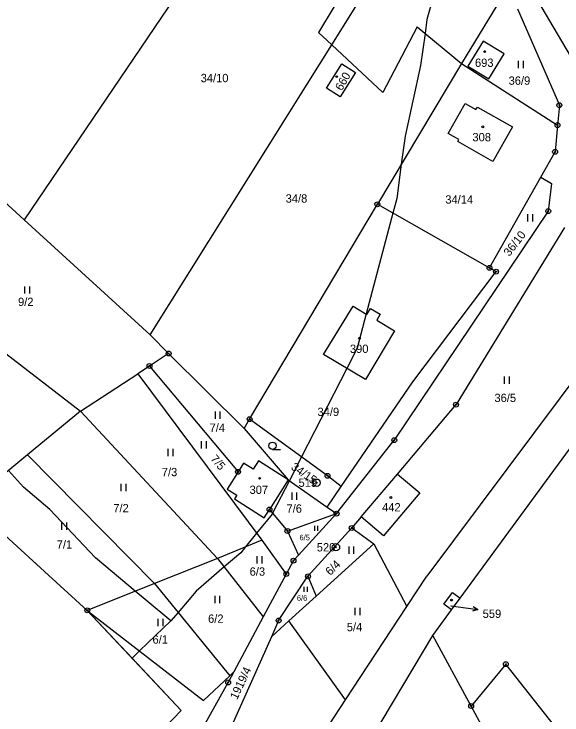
# Model space of a CAD drawing. Extents: x -445050 to -440454, y -1134563 to -1129741.
# Drawn here: x -442906.4 to -442794.3, y -1131013.5 to -1130870 of the extents above; entities that cross this region are included whole.
import ezdxf

# ---------------------------------------------------------------- set-up
doc = ezdxf.new("R2010")
doc.units = 0
for name, color, linetype in [('Vrstva 1', 7, 'Continuous'), ('Vrstva 13', 7, 'Continuous'), ('Vrstva 16', 7, 'Continuous'), ('Vrstva 17', 7, 'Continuous'), ('Vrstva 18', 7, 'Continuous'), ('Vrstva 19', 7, 'Continuous'), ('Vrstva 24', 7, 'Continuous'), ('Vrstva 25', 7, 'Continuous'), ('Vrstva 3', 7, 'Continuous'), ('Vrstva 37', 7, 'Continuous'), ('Vrstva 52', 7, 'Continuous')]:
    doc.layers.add(name, color=color, linetype=linetype)

msp = doc.modelspace()

# ---------------------------------------------------------------- linework, layer by layer
at = {"layer": 'Vrstva 1'}
for p, q in [((-442861.86, -1130849.44), (-442904.31, -1130912.16)), ((-442810.44, -1130875.57), (-442813.56, -1130880.71)), ((-442806.16, -1130878.16), (-442810.44, -1130875.57)), ((-442809.29, -1130883.3), (-442806.16, -1130878.16)), ((-442813.56, -1130880.71), (-442809.29, -1130883.3))]:
    msp.add_line(p, q, dxfattribs=at)
for points in [[(-442841.41, -1130876.33), (-442815.8, -1130835.42)], [(-442828.1, -1130847.15), (-442844.09, -1130873.84)], [(-442804.94, -1130863.83), (-442814.89, -1130880.18)], [(-442800.19, -1130865.72), (-442789.28, -1130884.24)], [(-442803.42, -1130868.95), (-442794.84, -1130888.7)], [(-442823.94, -1130872.69), (-442830.94, -1130886.07)], [(-442823.94, -1130872.69), (-442814.89, -1130880.18)], [(-442841.41, -1130876.33), (-442844.09, -1130873.84)], [(-442846.45, -1130884.39), (-442841.41, -1130876.33)], [(-442830.94, -1130886.07), (-442841.41, -1130876.33)], [(-442842.49, -1130885.21), (-442839.35, -1130880.2)], [(-442839.35, -1130880.2), (-442836.53, -1130881.97)], [(-442814.89, -1130880.18), (-442832.06, -1130908.96)], [(-442814.89, -1130880.18), (-442795.21, -1130892.76)], [(-442836.53, -1130881.97), (-442839.67, -1130886.99)], [(-442878.56, -1130935.7), (-442846.45, -1130884.39)], [(-442839.67, -1130886.99), (-442842.49, -1130885.21)], [(-442817.57, -1130894.46), (-442814.08, -1130888.34)], [(-442814.08, -1130888.34), (-442811.9, -1130889.58)], [(-442794.84, -1130888.7), (-442795.21, -1130892.76)], [(-442811.9, -1130889.58), (-442811.6, -1130889.06)], [(-442811.6, -1130889.06), (-442804.43, -1130893.14)], [(-442804.43, -1130893.14), (-442808.46, -1130900.22)], [(-442795.21, -1130892.76), (-442795.71, -1130898.24)], [(-442815.38, -1130895.71), (-442817.57, -1130894.46)], [(-442815.63, -1130896.14), (-442815.38, -1130895.71)], [(-442808.46, -1130900.22), (-442815.63, -1130896.14)], [(-442798.63, -1130903.39), (-442795.71, -1130898.24)], [(-442809.14, -1130921.97), (-442798.63, -1130903.39)], [(-442798.63, -1130903.39), (-442796.47, -1130904.73)], [(-442910.91, -1130906.11), (-442904.31, -1130912.16)], [(-442796.47, -1130904.73), (-442797.11, -1130910.38)], [(-442858.2, -1130952.92), (-442832.06, -1130908.96)], [(-442832.06, -1130908.96), (-442809.14, -1130921.97)], [(-442797.11, -1130910.38), (-442828.61, -1130957.23)], [(-442904.31, -1130912.16), (-442878.56, -1130935.7)], [(-442793.77, -1130913.74), (-442815.97, -1130949.95)], [(-442772.87, -1130919.37), (-442821.98, -1130985.08)], [(-442929.68, -1130922.83), (-442892.79, -1130951.31)], [(-442824.84, -1130945.29), (-442807.79, -1130922.74)], [(-442809.14, -1130921.97), (-442807.79, -1130922.74)], [(-442843.07, -1130939.7), (-442837, -1130929.82)], [(-442837, -1130929.82), (-442834.19, -1130931.5)], [(-442834.19, -1130931.5), (-442833.46, -1130930.29)], [(-442833.46, -1130930.29), (-442831.47, -1130931.47)], [(-442831.47, -1130931.47), (-442832.2, -1130932.69)], [(-442832.2, -1130932.69), (-442828.56, -1130934.85)], [(-442878.56, -1130935.7), (-442874.76, -1130939.49)], [(-442828.56, -1130934.85), (-442834.49, -1130944.81)], [(-442815.11, -1130989.54), (-442775.83, -1130936)], [(-442874.76, -1130939.49), (-442878.66, -1130942.05)], [(-442874.76, -1130939.49), (-442859.34, -1130954.86)], [(-442834.49, -1130944.81), (-442843.07, -1130939.7)], [(-442878.66, -1130942.05), (-442881.05, -1130943.62)], [(-442878.66, -1130942.05), (-442860.57, -1130963.71)], [(-442892.79, -1130951.31), (-442881.05, -1130943.62)], [(-442881.05, -1130943.62), (-442855.7, -1130977.68)], [(-442839.48, -1130966.72), (-442824.84, -1130945.29)], [(-442827.97, -1130964.15), (-442815.97, -1130949.95)], [(-442892.79, -1130951.31), (-442903.63, -1130960.22)], [(-442864.74, -1130981.44), (-442892.79, -1130951.31)], [(-442859.34, -1130954.86), (-442858.2, -1130952.92)], [(-442842.26, -1130964.51), (-442858.2, -1130952.92)], [(-442859.34, -1130954.86), (-442850.29, -1130965.33)], [(-442840.41, -1130972.26), (-442828.61, -1130957.23)], [(-442903.63, -1130960.22), (-442915.59, -1130970.05)], [(-442877.63, -1130986.57), (-442903.63, -1130960.22)], [(-442859.43, -1130961.91), (-442860.57, -1130963.71)], [(-442857.45, -1130963.17), (-442859.43, -1130961.91)], [(-442856.37, -1130961.48), (-442857.45, -1130963.17)], [(-442850.29, -1130965.33), (-442856.37, -1130961.48)], [(-442860.57, -1130963.71), (-442862.8, -1130967.23)], [(-442839.48, -1130966.72), (-442842.26, -1130964.51)], [(-442835.4, -1130972.93), (-442827.97, -1130964.15)], [(-442827.97, -1130964.15), (-442823.39, -1130968.02)], [(-442850.29, -1130965.33), (-442854.14, -1130971.41)], [(-442850.29, -1130965.33), (-442842.34, -1130970.91)], [(-442862.8, -1130967.23), (-442860.82, -1130968.49)], [(-442842.34, -1130970.91), (-442839.48, -1130966.72)], [(-442860.82, -1130968.49), (-442861.3, -1130969.25)], [(-442861.3, -1130969.25), (-442855.22, -1130973.1)], [(-442823.39, -1130968.02), (-442830.82, -1130976.8)], [(-442855.22, -1130973.1), (-442854.14, -1130971.41)], [(-442854.14, -1130971.41), (-442850.46, -1130975.82)], [(-442842.34, -1130970.91), (-442840.41, -1130972.26)], [(-442850.46, -1130975.82), (-442840.41, -1130972.26)], [(-442848.23, -1130980.78), (-442840.41, -1130972.26)], [(-442835.4, -1130972.93), (-442837.31, -1130975.19)], [(-442830.82, -1130976.8), (-442835.4, -1130972.93)], [(-442850.46, -1130975.82), (-442848.23, -1130980.78)], [(-442837.31, -1130975.19), (-442846.26, -1130985.08)], [(-442837.31, -1130975.19), (-442832.78, -1130978.42)], [(-442855.7, -1130977.68), (-442864.74, -1130981.44)], [(-442855.7, -1130977.68), (-442850.7, -1130984.61)], [(-442844.6, -1130989.14), (-442832.78, -1130978.42)], [(-442832.78, -1130978.42), (-442826.03, -1130991.26)], [(-442864.74, -1130981.44), (-442877.63, -1130986.57)], [(-442864.74, -1130981.44), (-442855.41, -1130993.4)], [(-442849.23, -1130981.87), (-442850.7, -1130984.61)], [(-442849.23, -1130981.87), (-442848.23, -1130980.78)], [(-442850.7, -1130984.61), (-442855.41, -1130993.4)], [(-442852.26, -1130994.12), (-442846.26, -1130985.08)], [(-442846.26, -1130985.08), (-442844.6, -1130989.14)], [(-442826.03, -1130991.26), (-442821.98, -1130985.08)], [(-442877.63, -1130986.57), (-442891.39, -1130992.04)], [(-442877.63, -1130986.57), (-442862.27, -1131005.42)], [(-442850.2, -1130994.22), (-442844.6, -1130989.14)], [(-442818.49, -1130990.78), (-442816.72, -1130988.36)], [(-442816.72, -1130988.36), (-442815.11, -1130989.54)], [(-442816.88, -1130991.96), (-442815.11, -1130989.54)], [(-442891.39, -1130992.04), (-442867.66, -1131010.46)], [(-442838.56, -1131010.38), (-442826.03, -1130991.26)], [(-442820.71, -1130997.18), (-442816.88, -1130991.96)], [(-442816.88, -1130991.96), (-442818.49, -1130990.78)], [(-442855.41, -1130993.4), (-442861.42, -1131004.62)], [(-442852.26, -1130994.12), (-442853.74, -1130997.43)], [(-442853.74, -1130997.43), (-442850.2, -1130994.22)], [(-442838.56, -1131010.38), (-442850.2, -1130994.22)], [(-442853.74, -1130997.43), (-442865.98, -1131024.86)], [(-442833.2, -1131018.12), (-442820.71, -1130997.18)], [(-442812.87, -1131011.62), (-442820.71, -1130997.18)], [(-442805.78, -1131003.06), (-442812.87, -1131011.62)], [(-442793.04, -1131019.25), (-442805.78, -1131003.06)], [(-442861.42, -1131004.62), (-442862.58, -1131006.79)], [(-442862.27, -1131005.42), (-442861.42, -1131004.62)], [(-442867.66, -1131010.46), (-442862.27, -1131005.42)], [(-442873.47, -1131026.38), (-442862.58, -1131006.79)], [(-442859, -1131041.59), (-442838.56, -1131010.38)], [(-442803.93, -1131028.07), (-442812.87, -1131011.62)]]:
    msp.add_lwpolyline(points, dxfattribs=at)
at = {"layer": 'Vrstva 13'}
for points in [[(-442899.33, -1130984.82), (-442915.59, -1130970.05)], [(-442895.35, -1130988.44), (-442899.33, -1130984.82)], [(-442891.39, -1130992.04), (-442895.35, -1130988.44)], [(-442891.39, -1130992.04), (-442872.21, -1131012.5)], [(-442872.21, -1131012.5), (-442878.7, -1131019.3)]]:
    msp.add_lwpolyline(points, dxfattribs=at)
at = {"layer": 'Vrstva 16'}
msp.add_line((-442814.5, -1130991.47), (-442811.53, -1130991.88), dxfattribs=at)
for points in [[(-442817.02, -1130991.12), (-442814.5, -1130991.47)], [(-442812.45, -1130991.25), (-442811.53, -1130991.88), (-442812.59, -1130992.24)]]:
    msp.add_lwpolyline(points, dxfattribs=at)
at = {"layer": 'Vrstva 24'}
for centre, radius in [((-442794.84, -1130888.7), 0.5), ((-442794.84, -1130888.7), 0.1), ((-442795.21, -1130892.76), 0.5), ((-442795.21, -1130892.76), 0.1), ((-442795.71, -1130898.24), 0.5), ((-442795.71, -1130898.24), 0.1), ((-442832.06, -1130908.96), 0.5), ((-442832.06, -1130908.96), 0.1), ((-442797.11, -1130910.38), 0.5), ((-442797.11, -1130910.38), 0.1), ((-442809.14, -1130921.97), 0.5), ((-442809.14, -1130921.97), 0.1), ((-442807.79, -1130922.74), 0.5), ((-442807.79, -1130922.74), 0.1), ((-442874.76, -1130939.49), 0.5), ((-442874.76, -1130939.49), 0.1), ((-442878.66, -1130942.05), 0.5), ((-442878.66, -1130942.05), 0.1), ((-442815.97, -1130949.95), 0.5), ((-442815.97, -1130949.95), 0.1), ((-442858.2, -1130952.92), 0.5), ((-442858.2, -1130952.92), 0.1), ((-442828.61, -1130957.23), 0.5), ((-442828.61, -1130957.23), 0.1), ((-442860.57, -1130963.71), 0.5), ((-442860.57, -1130963.71), 0.1), ((-442842.26, -1130964.51), 0.5), ((-442842.26, -1130964.51), 0.1), ((-442844.5, -1130965.92), 0.75), ((-442844.5, -1130965.92), 0.1), ((-442854.14, -1130971.41), 0.5), ((-442854.14, -1130971.41), 0.1), ((-442840.41, -1130972.26), 0.5), ((-442840.41, -1130972.26), 0.1), ((-442837.31, -1130975.19), 0.5), ((-442850.46, -1130975.82), 0.5), ((-442850.46, -1130975.82), 0.1), ((-442837.31, -1130975.19), 0.1), ((-442840.53, -1130979.14), 0.75), ((-442840.53, -1130979.14), 0.1), ((-442849.23, -1130981.87), 0.5), ((-442849.23, -1130981.87), 0.1), ((-442850.7, -1130984.61), 0.5), ((-442850.7, -1130984.61), 0.1), ((-442846.26, -1130985.08), 0.5), ((-442846.26, -1130985.08), 0.1), ((-442891.39, -1130992.04), 0.5), ((-442891.39, -1130992.04), 0.1), ((-442852.26, -1130994.12), 0.5), ((-442852.26, -1130994.12), 0.1), ((-442805.78, -1131003.06), 0.5), ((-442805.78, -1131003.06), 0.1), ((-442862.58, -1131006.79), 0.5), ((-442862.58, -1131006.79), 0.1), ((-442812.87, -1131011.62), 0.5), ((-442812.87, -1131011.62), 0.1)]:
    msp.add_circle(centre, radius, dxfattribs=at)
at = {"layer": 'Vrstva 25'}
for p, q in [((-442803.19, -1130881.11), (-442803.19, -1130879.61)), ((-442802.19, -1130881.11), (-442802.19, -1130879.61)), ((-442801.28, -1130912.47), (-442801.28, -1130910.97)), ((-442800.28, -1130912.47), (-442800.28, -1130910.97)), ((-442904.14, -1130927.25), (-442904.14, -1130925.75)), ((-442903.14, -1130927.25), (-442903.14, -1130925.75)), ((-442806.07, -1130945.7), (-442806.07, -1130944.2)), ((-442805.07, -1130945.7), (-442805.07, -1130944.2)), ((-442865.19, -1130952.88), (-442865.19, -1130951.38)), ((-442864.19, -1130952.88), (-442864.19, -1130951.38)), ((-442868.04, -1130958.95), (-442868.04, -1130957.45)), ((-442867.04, -1130958.95), (-442867.04, -1130957.45)), ((-442874.83, -1130960.47), (-442874.83, -1130958.97)), ((-442873.83, -1130960.47), (-442873.83, -1130958.97)), ((-442853.51, -1130959.11), (-442851.91, -1130959.11)), ((-442884.47, -1130967.66), (-442884.47, -1130966.16)), ((-442883.47, -1130967.66), (-442883.47, -1130966.16)), ((-442849.52, -1130969.41), (-442849.52, -1130967.91)), ((-442848.52, -1130969.41), (-442848.52, -1130967.91)), ((-442896.59, -1130975.58), (-442896.59, -1130974.08)), ((-442895.59, -1130975.58), (-442895.59, -1130974.08)), ((-442844.88, -1130975.75), (-442844.88, -1130974.75)), ((-442844.21, -1130975.75), (-442844.21, -1130974.75)), ((-442837.85, -1130980.48), (-442837.85, -1130978.98)), ((-442836.85, -1130980.48), (-442836.85, -1130978.98)), ((-442856.62, -1130982.49), (-442856.62, -1130980.99)), ((-442855.62, -1130982.49), (-442855.62, -1130980.99)), ((-442847.04, -1130988.24), (-442847.04, -1130987.24)), ((-442846.36, -1130988.24), (-442846.36, -1130987.24)), ((-442865.26, -1130990.59), (-442865.26, -1130989.09)), ((-442864.26, -1130990.59), (-442864.26, -1130989.09)), ((-442836.58, -1130993.02), (-442836.58, -1130991.52)), ((-442835.58, -1130993.02), (-442835.58, -1130991.52)), ((-442876.91, -1130995.28), (-442876.91, -1130993.78)), ((-442875.91, -1130995.28), (-442875.91, -1130993.78))]:
    msp.add_line(p, q, dxfattribs=at)
for centre, radius in [((-442810.12, -1130877.71), 0.175), ((-442840.38, -1130882.85), 0.175), ((-442810.5, -1130893.12), 0.175), ((-442835.74, -1130936.38), 0.175), ((-442853.51, -1130958.36), 0.75), ((-442856.15, -1130965.02), 0.175), ((-442829.3, -1130968.95), 0.175), ((-442816.89, -1130989.94), 0.175)]:
    msp.add_circle(centre, radius, dxfattribs=at)
at = {"layer": 'Vrstva 3'}
for points in [[(-442810.44, -1130875.57), (-442813.56, -1130880.71)], [(-442806.16, -1130878.16), (-442810.44, -1130875.57)], [(-442809.29, -1130883.3), (-442806.16, -1130878.16)], [(-442842.49, -1130885.21), (-442839.35, -1130880.2)], [(-442839.35, -1130880.2), (-442836.53, -1130881.97)], [(-442813.56, -1130880.71), (-442809.29, -1130883.3)], [(-442836.53, -1130881.97), (-442839.67, -1130886.99)], [(-442839.67, -1130886.99), (-442842.49, -1130885.21)], [(-442817.57, -1130894.46), (-442814.08, -1130888.34)], [(-442814.08, -1130888.34), (-442811.9, -1130889.58)], [(-442811.9, -1130889.58), (-442811.6, -1130889.06)], [(-442811.6, -1130889.06), (-442804.43, -1130893.14)], [(-442804.43, -1130893.14), (-442808.46, -1130900.22)], [(-442815.38, -1130895.71), (-442817.57, -1130894.46)], [(-442815.63, -1130896.14), (-442815.38, -1130895.71)], [(-442808.46, -1130900.22), (-442815.63, -1130896.14)], [(-442843.07, -1130939.7), (-442837, -1130929.82)], [(-442837, -1130929.82), (-442834.19, -1130931.5)], [(-442834.19, -1130931.5), (-442833.46, -1130930.29)], [(-442833.46, -1130930.29), (-442831.47, -1130931.47)], [(-442831.47, -1130931.47), (-442832.2, -1130932.69)], [(-442832.2, -1130932.69), (-442828.56, -1130934.85)], [(-442828.56, -1130934.85), (-442834.49, -1130944.81)], [(-442834.49, -1130944.81), (-442843.07, -1130939.7)], [(-442859.43, -1130961.91), (-442860.57, -1130963.71)], [(-442857.45, -1130963.17), (-442859.43, -1130961.91)], [(-442856.37, -1130961.48), (-442857.45, -1130963.17)], [(-442850.29, -1130965.33), (-442856.37, -1130961.48)], [(-442860.57, -1130963.71), (-442862.8, -1130967.23)], [(-442835.4, -1130972.93), (-442827.97, -1130964.15)], [(-442827.97, -1130964.15), (-442823.39, -1130968.02)], [(-442850.29, -1130965.33), (-442854.14, -1130971.41)], [(-442862.8, -1130967.23), (-442860.82, -1130968.49)], [(-442860.82, -1130968.49), (-442861.3, -1130969.25)], [(-442861.3, -1130969.25), (-442855.22, -1130973.1)], [(-442823.39, -1130968.02), (-442830.82, -1130976.8)], [(-442855.22, -1130973.1), (-442854.14, -1130971.41)], [(-442830.82, -1130976.8), (-442835.4, -1130972.93)], [(-442818.49, -1130990.78), (-442816.72, -1130988.36)], [(-442816.72, -1130988.36), (-442815.11, -1130989.54)], [(-442816.88, -1130991.96), (-442815.11, -1130989.54)], [(-442816.88, -1130991.96), (-442818.49, -1130990.78)]]:
    msp.add_lwpolyline(points, dxfattribs=at)
at = {"layer": 'Vrstva 37'}
for centre in [(-442810.12, -1130877.71), (-442840.38, -1130882.85), (-442810.5, -1130893.12), (-442835.74, -1130936.38), (-442856.15, -1130965.02), (-442829.3, -1130968.95), (-442816.89, -1130989.94)]:
    msp.add_circle(centre, 0.175, dxfattribs=at)
at = {"layer": 'Vrstva 52'}
for points in [[(-442820.02, -1130864.39), (-442821.94, -1130871.19), (-442822.32, -1130874.03), (-442823.21, -1130880.55), (-442826.4, -1130895), (-442827.17, -1130900.76), (-442828.1, -1130907.76), (-442828.89, -1130910.76), (-442834.34, -1130931.41), (-442836.18, -1130938.37), (-442838.31, -1130942.53), (-442847.59, -1130960.64), (-442850.07, -1130965.48), (-442853.5, -1130972.17), (-442853.61, -1130972.38), (-442856.76, -1130976.26), (-442859.03, -1130979.06), (-442859.99, -1130980.25), (-442863.39, -1130983.17), (-442869.13, -1130988.11), (-442872.84, -1130992.45), (-442874.33, -1130994.19)], [(-442882.23, -1131001.82), (-442891.39, -1130992.04), (-442895.35, -1130988.44), (-442899.33, -1130984.82), (-442906.63, -1130978.19), (-442915.59, -1130970.05), (-442919.98, -1130966.06), (-442940.07, -1130948.87), (-442946.49, -1130943.37), (-442949.68, -1130940.64), (-442952.16, -1130938.52), (-442960.65, -1130932.13), (-442970.89, -1130924.41), (-442971.95, -1130923.61), (-442972.2, -1130923.41), (-442974.22, -1130921.83), (-442988, -1130911.01), (-443002.15, -1130899.89), (-443003.41, -1130898.87), (-443009.46, -1130894.01), (-443030.66, -1130876.94)], [(-442874.33, -1130994.19), (-442879.16, -1130990.16), (-442881.58, -1130988.14), (-442889.75, -1130981.31), (-442899.05, -1130971.44), (-442904.42, -1130966.86), (-442907.51, -1130963.41)], [(-442874.33, -1130994.19), (-442879.01, -1130998.71), (-442880.7, -1131000.34), (-442882.23, -1131001.82)], [(-442914.32, -1131061.21), (-442904.54, -1131049.3), (-442887.1, -1131028.05), (-442882.25, -1131023), (-442879.56, -1131020.2), (-442878.7, -1131019.3), (-442872.21, -1131012.5), (-442882.23, -1131001.82)]]:
    msp.add_lwpolyline(points, dxfattribs=at)

# ---------------------------------------------------------------- texts
at = {"layer": 'Vrstva 16'}
msp.add_text('559', height=1.7, dxfattribs=at).set_placement((-442810.53, -1130993.58))
at = {"layer": 'Vrstva 17'}
for s, p in [('519', (-442848.19, -1130966.77)), ('520', (-442844.46, -1130979.99))]:
    msp.add_text(s, height=1.7, dxfattribs=at).set_placement(p)
at = {"layer": 'Vrstva 18'}
for s, height, p in [('34/10', 1.7, (-442868.21, -1130883.98)), ('36/9', 1.7, (-442805.22, -1130884.51)), ('34/8', 1.7, (-442850.82, -1130908.62)), ('34/14', 1.7, (-442818.17, -1130908.83)), ('9/2', 1.7, (-442905.56, -1130929.78)), ('36/5', 1.7, (-442808.12, -1130949.42)), ('34/9', 1.7, (-442844.31, -1130952.28)), ('7/4', 1.7, (-442866.39, -1130955.53)), ('7/3', 1.7, (-442876.16, -1130964.6)), ('7/2', 1.7, (-442886.08, -1130971.98)), ('7/6', 1.7, (-442850.65, -1130972.06)), ('7/1', 1.7, (-442897.65, -1130979.41)), ('6/5', 1.14, (-442847.99, -1130977.71)), ('6/3', 1.7, (-442858.19, -1130984.95)), ('6/6', 1.14, (-442848.53, -1130990.1)), ('6/2', 1.7, (-442866.69, -1130994.59)), ('5/4', 1.7, (-442838.32, -1130996.31)), ('6/1', 1.7, (-442878.06, -1130998.86))]:
    msp.add_text(s, height=height, dxfattribs=at).set_placement(p)
for s, rotation, p in [('36/10', 52.3763, (-442805.06, -1130919.74)), ('7/5', 310.306, (-442866.31, -1130961.12)), ('34/15', 325.305, (-442849.88, -1130963.07)), ('6/4', 45.2159, (-442841.68, -1130985.03)), ('1919/4', 64.7897, (-442860.76, -1131010.43))]:
    msp.add_text(s, height=1.7, rotation=rotation, dxfattribs=at).set_placement(p)
at = {"layer": 'Vrstva 19'}
for s, height, p in [('693', 1.7, (-442812.1, -1130880.85)), ('308', 1.7, (-442812.62, -1130896.08)), ('390', 1.7, (-442837.68, -1130939.38)), ('307', 1.7, (-442858.21, -1130968.22)), ('442', 1.7, (-442831.1, -1130971.8)), ('559', 0.1, (-442817.12, -1130991.12))]:
    msp.add_text(s, height=height, dxfattribs=at).set_placement(p)
msp.add_text('660', height=1.7, rotation=60.4397, dxfattribs=at).set_placement((-442839.34, -1130885.86))

doc.saveas('drawing.dxf')
